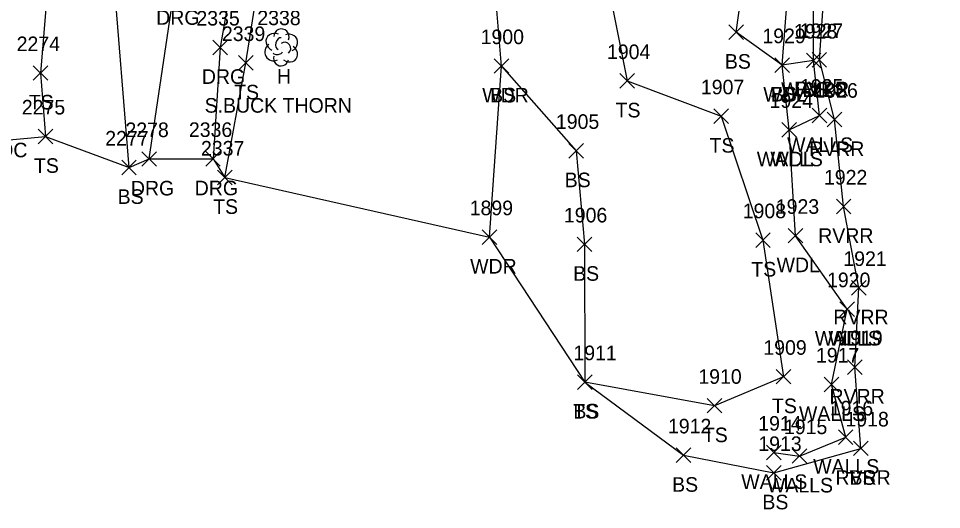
# Model space of a CAD drawing. Extents: x 1461855 to 1464118, y 556196 to 557441.
# Drawn here: x 1462039.2 to 1462165.9, y 556319.8 to 556387.1 of the extents above; entities that cross this region are included whole.
import ezdxf

# ---------------------------------------------------------------- set-up
doc = ezdxf.new("R2010")
doc.units = 0
for name, color, linetype in [('L_A', 7, 'Continuous'), ('L_C', 7, 'Continuous'), ('L_I', 7, 'Continuous'), ('L_TIC', 7, 'Continuous'), ('LAWA', 7, 'Continuous'), ('LAWE', 7, 'Continuous'), ('LELB', 7, 'Continuous'), ('LSOGP', 7, 'Continuous'), ('LTD', 7, 'Continuous'), ('LWS', 7, 'Continuous'), ('R_A', 7, 'Continuous'), ('R_I', 7, 'Continuous'), ('R_TIC', 7, 'Continuous'), ('RDG', 7, 'Continuous')]:
    doc.layers.add(name, color=color, linetype=linetype)

msp = doc.modelspace()

# ---------------------------------------------------------------- linework, layer by layer
at = {"layer": 'L_TIC'}
for points in [[(1462136.75, 556384.25), (1462138.75, 556386.25)], [(1462138.75, 556384.25), (1462136.75, 556386.25)], [(1462069.43, 556380.04), (1462071.43, 556382.04)], [(1462071.43, 556380.04), (1462069.43, 556382.04)], [(1462143.04, 556379.75), (1462145.04, 556381.75)], [(1462145.04, 556379.75), (1462143.04, 556381.75)], [(1462143.04, 556379.75), (1462145.04, 556381.75)], [(1462145.04, 556379.75), (1462143.04, 556381.75)], [(1462147.37, 556380.38), (1462149.37, 556382.38)], [(1462149.37, 556380.38), (1462147.37, 556382.38)], [(1462147.37, 556380.38), (1462149.37, 556382.38)], [(1462149.37, 556380.38), (1462147.37, 556382.38)], [(1462148.16, 556380.46), (1462150.16, 556382.46)], [(1462150.16, 556380.46), (1462148.16, 556382.46)], [(1462041.25, 556378.66), (1462043.25, 556380.66)], [(1462043.25, 556378.66), (1462041.25, 556380.66)], [(1462104.53, 556379.62), (1462106.53, 556381.62)], [(1462106.53, 556379.62), (1462104.53, 556381.62)], [(1462104.53, 556379.62), (1462106.53, 556381.62)], [(1462106.53, 556379.62), (1462104.53, 556381.62)], [(1462121.78, 556377.57), (1462123.78, 556379.57)], [(1462123.78, 556377.57), (1462121.78, 556379.57)], [(1462134.68, 556372.74), (1462136.68, 556374.74)], [(1462136.68, 556372.74), (1462134.68, 556374.74)], [(1462148.19, 556372.82), (1462150.19, 556374.82)], [(1462150.19, 556372.82), (1462148.19, 556374.82)], [(1462150.24, 556372.27), (1462152.24, 556374.27)], [(1462152.24, 556372.27), (1462150.24, 556374.27)], [(1462144.02, 556370.87), (1462146.02, 556372.87)], [(1462146.02, 556370.87), (1462144.02, 556372.87)], [(1462144.02, 556370.87), (1462146.02, 556372.87)], [(1462146.02, 556370.87), (1462144.02, 556372.87)], [(1462041.96, 556369.97), (1462043.96, 556371.97)], [(1462043.96, 556369.97), (1462041.96, 556371.97)], [(1462114.77, 556368), (1462116.77, 556370)], [(1462116.77, 556368), (1462114.77, 556370)], [(1462053.41, 556365.71), (1462055.41, 556367.71)], [(1462055.41, 556365.71), (1462053.41, 556367.71)], [(1462066.55, 556364.34), (1462068.55, 556366.34)], [(1462068.55, 556364.34), (1462066.55, 556366.34)], [(1462151.49, 556360.37), (1462153.49, 556362.37)], [(1462153.49, 556360.37), (1462151.49, 556362.37)], [(1462102.87, 556356.16), (1462104.87, 556358.16)], [(1462104.87, 556356.16), (1462102.87, 556358.16)], [(1462140.42, 556355.75), (1462142.42, 556357.75)], [(1462142.42, 556355.75), (1462140.42, 556357.75)], [(1462144.87, 556356.35), (1462146.87, 556358.35)], [(1462146.87, 556356.35), (1462144.87, 556358.35)], [(1462115.92, 556355.17), (1462117.92, 556357.17)], [(1462117.92, 556355.17), (1462115.92, 556357.17)], [(1462153.57, 556349.2), (1462155.57, 556351.2)], [(1462155.57, 556349.2), (1462153.57, 556351.2)], [(1462151.98, 556346.29), (1462153.98, 556348.29)], [(1462153.98, 556346.29), (1462151.98, 556348.29)], [(1462151.98, 556346.29), (1462153.98, 556348.29)], [(1462153.98, 556346.29), (1462151.98, 556348.29)], [(1462153.04, 556338.34), (1462155.04, 556340.34)], [(1462155.04, 556338.34), (1462153.04, 556340.34)], [(1462143.25, 556337.02), (1462145.25, 556339.02)], [(1462145.25, 556337.02), (1462143.25, 556339.02)], [(1462115.96, 556336.28), (1462117.96, 556338.28)], [(1462117.96, 556336.28), (1462115.96, 556338.28)], [(1462115.96, 556336.28), (1462117.96, 556338.28)], [(1462117.96, 556336.28), (1462115.96, 556338.28)], [(1462149.82, 556335.96), (1462151.82, 556337.96)], [(1462151.82, 556335.96), (1462149.82, 556337.96)], [(1462133.76, 556333.04), (1462135.76, 556335.04)], [(1462135.76, 556333.04), (1462133.76, 556335.04)], [(1462151.77, 556328.71), (1462153.77, 556330.71)], [(1462153.77, 556328.71), (1462151.77, 556330.71)], [(1462141.9, 556326.62), (1462143.9, 556328.62)], [(1462143.9, 556326.62), (1462141.9, 556328.62)], [(1462153.86, 556327.19), (1462155.86, 556329.19)], [(1462155.86, 556327.19), (1462153.86, 556329.19)], [(1462153.86, 556327.19), (1462155.86, 556329.19)], [(1462155.86, 556327.19), (1462153.86, 556329.19)], [(1462129.51, 556326.24), (1462131.51, 556328.24)], [(1462131.51, 556326.24), (1462129.51, 556328.24)], [(1462145.42, 556326.14), (1462147.42, 556328.14)], [(1462147.42, 556326.14), (1462145.42, 556328.14)], [(1462141.9, 556323.83), (1462143.9, 556325.83)], [(1462143.9, 556323.83), (1462141.9, 556325.83)]]:
    msp.add_lwpolyline(points, dxfattribs=at)
at = {"layer": 'LAWA'}
for points in [[(1462103.87, 556357.16), (1462105.53, 556380.62), (1462104.39, 556394.37), (1462118.43, 556400.32), (1462128.68, 556394.64), (1462138.86, 556393.11), (1462145.16, 556394.92)], [(1462152.98, 556347.29), (1462145.87, 556357.35), (1462145.02, 556371.87), (1462144.04, 556380.75), (1462145.16, 556394.92)]]:
    msp.add_lwpolyline(points, dxfattribs=at)
at = {"layer": 'LAWE'}
msp.add_lwpolyline([(1462154.86, 556328.19), (1462154.04, 556339.34), (1462154.57, 556350.2), (1462152.49, 556361.37), (1462151.24, 556373.27), (1462149.16, 556381.46), (1462150.12, 556395.58), (1462150.66, 556404.99), (1462152.29, 556411.55), (1462152.85, 556416.04), (1462153.94, 556421.51), (1462155.97, 556453.8), (1462150.72, 556458.73), (1462147.2, 556465.73), (1462141.3, 556477.14), (1462134.96, 556494.77), (1462123.9, 556516.11), (1462120.54, 556522.08)], dxfattribs=at)
at = {"layer": 'LELB'}
for points in [[(1462054.41, 556366.71), (1462052.26, 556393.35), (1462054.18, 556399.68), (1462054.96, 556419.35), (1462044.26, 556430.59)], [(1461996.03, 556418.95), (1462014.06, 556419.67), (1462033.14, 556420.16), (1462043, 556412.96), (1462051.36, 556399.82), (1462043.66, 556396.81), (1462042.25, 556379.66), (1462042.96, 556370.97)], [(1462067.55, 556365.34), (1462070.43, 556381.04), (1462073.87, 556402.7), (1462075.31, 556410.13), (1462077.56, 556419.16), (1462088.19, 556417.5), (1462102.37, 556414.71), (1462109.91, 556404.12)], [(1462148.37, 556381.38), (1462144.04, 556380.75), (1462137.75, 556385.25), (1462138.86, 556393.11), (1462141.17, 556403.51), (1462143.91, 556407.09), (1462147.38, 556411.88)], [(1462118.43, 556400.32), (1462122.78, 556378.57), (1462135.68, 556373.74), (1462141.42, 556356.75), (1462144.25, 556338.02), (1462134.76, 556334.04), (1462116.96, 556337.28)], [(1462105.53, 556380.62), (1462115.77, 556369), (1462116.92, 556356.17), (1462116.96, 556337.28), (1462130.51, 556327.24), (1462142.9, 556324.83), (1462154.86, 556328.19)]]:
    msp.add_lwpolyline(points, dxfattribs=at)
at = {"layer": 'LSOGP'}
msp.add_lwpolyline([(1462020.07, 556368.85), (1462042.96, 556370.97), (1462054.41, 556366.71), (1462057.18, 556367.87), (1462065.94, 556367.89), (1462067.55, 556365.34), (1462103.87, 556357.16), (1462116.96, 556337.28), (1462130.51, 556327.24), (1462142.9, 556324.83), (1462154.86, 556328.19), (1462154.04, 556339.34), (1462154.57, 556350.2), (1462152.49, 556361.37), (1462151.24, 556373.27), (1462149.16, 556381.46), (1462150.12, 556395.58), (1462150.66, 556404.99), (1462152.29, 556411.55), (1462201.56, 556420.69)], dxfattribs=at)
at = {"layer": 'LTD'}
msp.add_line((1462075.28, 556383.22), (1462075.28, 556383.22), dxfattribs=at)
msp.add_line((1462075.28, 556383.22), (1462075.28, 556383.22), dxfattribs=at)
msp.add_arc((1462075.33, 556384.66), 1.05, 335.5272, 180.9563, dxfattribs=at)
for centre, major_axis, ratio, start_param, end_param in [((1462074.49, 556383.89), (1.21, -0.51), 0.895232, 1.570796, 4.712389), ((1462075.08, 556383.68), (-0.208, -0.792), 0.645439, 3.141593, 6.283185), ((1462076.33, 556383.81), (-1.14, -0.48), 0.949671, 1.570796, 4.712389), ((1462074.2, 556382.51), (0.58, -1.04), 0.959034, 3.141593, 6.283185), ((1462075.78, 556383.05), (-0.5, 0.667), 0.989748, 3.141593, 6.283185), ((1462076.28, 556382.39), (-1.09, 0.79), 0.841452, 1.570796, 4.712389), ((1462075.28, 556381.72), (0.26, 1.06), 0.942809, 1.570796, 4.712389), ((1462074.83, 556382.47), (-0.625, -0.083), 0.423636, 0, 3.141593)]:
    msp.add_ellipse(centre, major_axis=major_axis, ratio=ratio, start_param=start_param, end_param=end_param, dxfattribs=at)
at = {"layer": 'LWS'}
for points in [[(1462145.02, 556371.87), (1462149.19, 556373.82), (1462148.37, 556381.38), (1462148.3, 556395.31), (1462149.75, 556404.89), (1462151.03, 556411.67), (1462148.84, 556411.93)], [(1462142.9, 556327.62), (1462146.42, 556327.14), (1462152.77, 556329.71), (1462150.82, 556336.96), (1462152.98, 556347.29)]]:
    msp.add_lwpolyline(points, dxfattribs=at)
at = {"layer": 'R_TIC'}
for points in [[(1462065.92, 556382.17), (1462067.92, 556384.17)], [(1462067.92, 556382.17), (1462065.92, 556384.17)], [(1462056.18, 556366.87), (1462058.18, 556368.87)], [(1462058.18, 556366.87), (1462056.18, 556368.87)], [(1462064.94, 556366.89), (1462066.94, 556368.89)], [(1462066.94, 556366.89), (1462064.94, 556368.89)]]:
    msp.add_lwpolyline(points, dxfattribs=at)
at = {"layer": 'RDG'}
for points in [[(1462057.18, 556367.87), (1462060.66, 556391.27), (1462064.42, 556425.32)], [(1462073.51, 556425.14), (1462071.12, 556407.38), (1462066.92, 556383.17), (1462065.94, 556367.89)]]:
    msp.add_lwpolyline(points, dxfattribs=at)

# ---------------------------------------------------------------- texts
at = {"layer": 'L_A'}
for s, p in [('BS', (1462136.19, 556380.25)), ('H', (1462074.72, 556378.22)), ('TS', (1462068.84, 556376.04)), ('WALLS', (1462143.91, 556376.38)), ('RVRR', (1462145.67, 556376.46)), ('BS', (1462146.81, 556376.38)), ('TS', (1462040.66, 556374.66)), ('WDR', (1462102.89, 556375.62)), ('BS', (1462103.97, 556375.62)), ('WDL', (1462141.46, 556375.75)), ('BS', (1462142.49, 556375.75)), ('TS', (1462121.19, 556373.57)), ('TS', (1462134.09, 556368.74)), ('WALLS', (1462144.73, 556368.82)), ('RVRR', (1462147.75, 556368.27)), ('TS', (1462041.37, 556365.97)), ('WALLS', (1462140.57, 556366.87)), ('WDL', (1462142.44, 556366.87)), ('BS', (1462114.21, 556364)), ('BS', (1462052.85, 556361.71)), ('TS', (1462065.96, 556360.34)), ('RVRR', (1462149, 556356.37)), ('WDR', (1462101.23, 556352.16)), ('WDL', (1462143.29, 556352.35)), ('BS', (1462115.36, 556351.17)), ('TS', (1462139.82, 556351.75)), ('RVRR', (1462151.08, 556345.2)), ('WALLS', (1462148.53, 556342.29)), ('WDL', (1462150.4, 556342.29)), ('RVRR', (1462150.55, 556334.34)), ('TS', (1462142.66, 556333.02)), ('TS', (1462115.36, 556332.28)), ('BS', (1462115.4, 556332.28)), ('WALLS', (1462146.36, 556331.96)), ('TS', (1462133.17, 556329.04)), ('WALLS', (1462148.31, 556324.71)), ('RVRR', (1462151.37, 556323.19)), ('BS', (1462153.3, 556323.19)), ('BS', (1462128.95, 556322.24)), ('WALLS', (1462138.44, 556322.62)), ('WALLS', (1462141.97, 556322.14)), ('BS', (1462141.34, 556319.83))]:
    msp.add_text(s, height=2, dxfattribs=at).set_placement(p)
at = {"layer": 'L_C'}
for s, p in [('S.BUCK THORN', (1462064.79, 556374.22)), ('M.LOC', (1462032, 556368.1))]:
    msp.add_text(s, height=2, dxfattribs=at).set_placement(p)
at = {"layer": 'L_I'}
for s, p in [('2338', (1462072.02, 556386.22)), ('2339', (1462067.16, 556384.04)), ('1900', (1462102.67, 556383.62)), ('1900', (1462102.67, 556383.62)), ('1929', (1462141.34, 556383.75)), ('1929', (1462141.34, 556383.75)), ('1928', (1462145.67, 556384.38)), ('1928', (1462145.67, 556384.38)), ('1927', (1462146.47, 556384.46)), ('2274', (1462038.99, 556382.66)), ('1904', (1462120.01, 556381.57)), ('1907', (1462132.9, 556376.74)), ('1925', (1462146.5, 556376.82)), ('1926', (1462148.49, 556376.27)), ('1924', (1462142.33, 556374.87)), ('1924', (1462142.33, 556374.87)), ('2275', (1462039.7, 556373.97)), ('1905', (1462113, 556372)), ('2277', (1462051.15, 556369.71)), ('2337', (1462064.29, 556368.34)), ('1922', (1462149.79, 556364.37)), ('1899', (1462101.17, 556360.16)), ('1908', (1462138.64, 556359.75)), ('1923', (1462143.18, 556360.35)), ('1906', (1462114.1, 556359.17)), ('1921', (1462152.45, 556353.2)), ('1920', (1462150.21, 556350.29)), ('1920', (1462150.21, 556350.29)), ('1919', (1462151.9, 556342.34)), ('1909', (1462141.47, 556341.02)), ('1911', (1462115.4, 556340.28)), ('1911', (1462115.4, 556340.28)), ('1917', (1462148.69, 556339.96)), ('1910', (1462132.55, 556337.04)), ('1916', (1462150.59, 556332.71)), ('1914', (1462140.77, 556330.62)), ('1918', (1462152.74, 556331.19)), ('1918', (1462152.74, 556331.19)), ('1912', (1462128.38, 556330.24)), ('1915', (1462144.3, 556330.14)), ('1913', (1462140.78, 556327.83))]:
    msp.add_text(s, height=2, dxfattribs=at).set_placement(p)
at = {"layer": 'R_A'}
for p in [(1462058.14, 556386.27), (1462064.41, 556378.17), (1462054.67, 556362.87), (1462063.43, 556362.89)]:
    msp.add_text('DRG', height=2, dxfattribs=at).set_placement(p)
at = {"layer": 'R_I'}
for s, p in [('2335', (1462063.66, 556386.17)), ('2278', (1462053.92, 556370.87)), ('2336', (1462062.63, 556370.89))]:
    msp.add_text(s, height=2, dxfattribs=at).set_placement(p)

doc.saveas('drawing.dxf')
